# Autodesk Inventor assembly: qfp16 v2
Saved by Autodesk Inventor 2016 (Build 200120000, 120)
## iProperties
Created: 2016-09
Part Number: qfp16 v2
Document SubType Name: Assembly
Designer: Administrator
Author: Administrator
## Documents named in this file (3)
- c:\worker\convert-fusion-aug-2016\tmp\job-1\13\output\files\2055b865-881d-4af8-ae30-e7b46ec3c804\qfp16 v2.iam
- c:\worker\convert-fusion-aug-2016\tmp\job-1\13\output\files\2055b865-881d-4af8-ae30-e7b46ec3c804\Component21.ipt
- c:\worker\convert-fusion-aug-2016\tmp\job-1\13\output\files\2055b865-881d-4af8-ae30-e7b46ec3c804\lead.ipt
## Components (2 placed, 2 different names)
1. Component21:1
2. lead:1
